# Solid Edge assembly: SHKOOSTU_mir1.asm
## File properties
Author: Türk
Template: Iso Assembly.asm
Last saved by: Türk
Revision: 2
Application: Solid Edge
Username: Türk
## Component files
Esimene vedru_mir.par
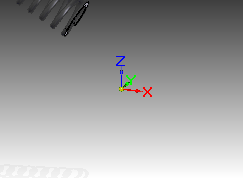
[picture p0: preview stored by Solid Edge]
